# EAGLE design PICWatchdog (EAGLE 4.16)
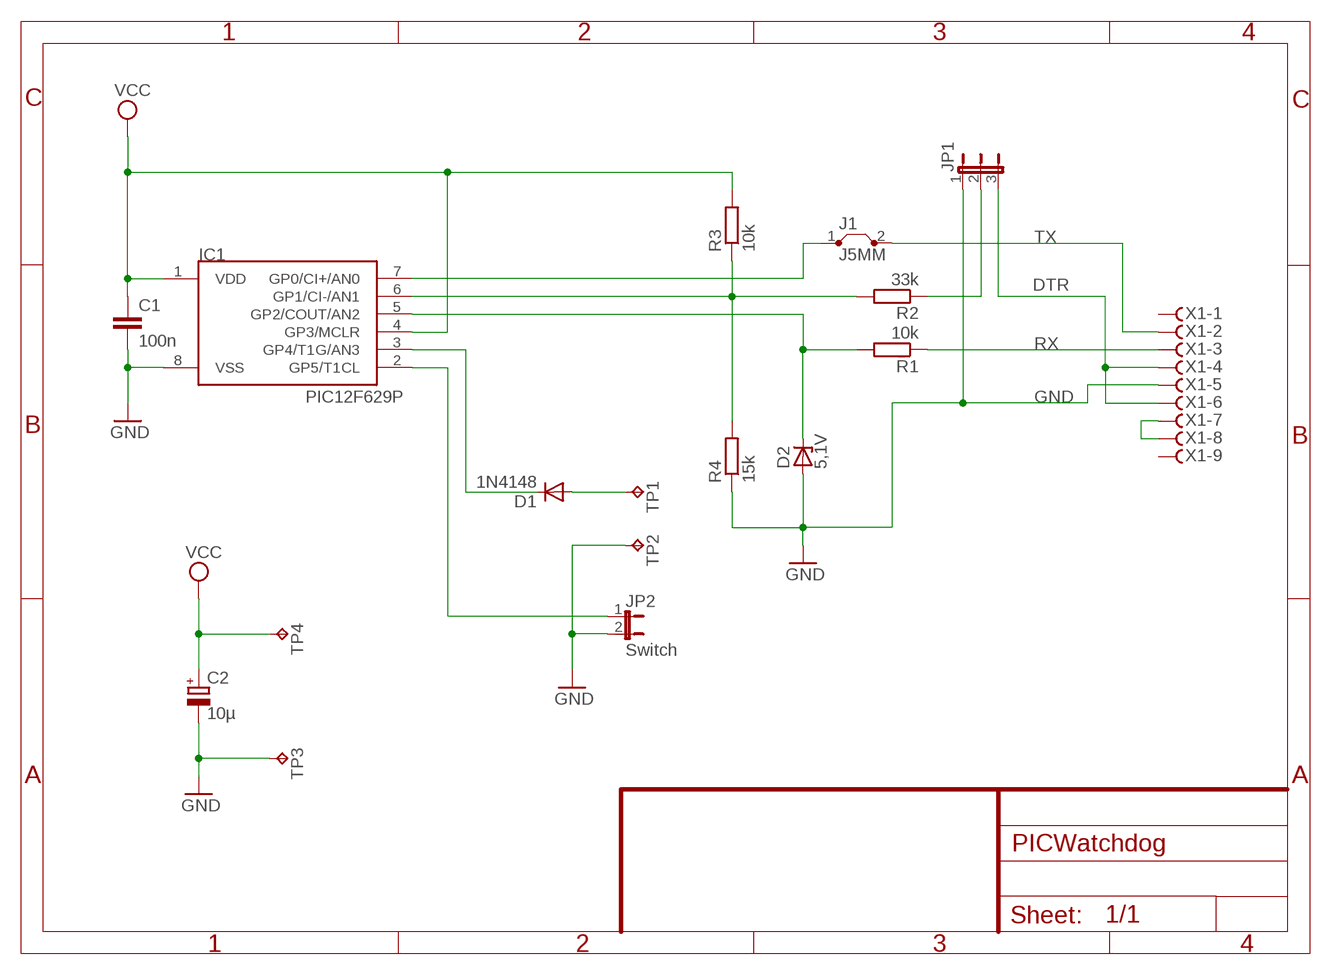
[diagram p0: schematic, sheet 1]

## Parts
C1  100n  C-EU050-030X075  [C050-030X075]
C2  10µ  CPOL-EUE2.5-6  [E2,5-6]
D1  1N4148  [DO35-10]
D2  5,1V  ZENER-DIODEDO34-7  [DO34Z7]
IC1  PIC12F629P  [DIL8]
J1  J5MM  [05]
JP1  JP2E  [JP2]
JP2  Switch  JP1E  [JP1]
R1  10k  R-EU_0207/12  [0207/12]
R2  33k  R-EU_0207/12  [0207/12]
R3  10k  R-EU_0207/12  [0207/12]
R4  15k  R-EU_0207/12  [0207/12]
TP1  TPPAD1-17Y  [P1-17Y]
TP2  TPPAD1-17Y  [P1-17Y]
TP3  TPPAD1-17Y  [P1-17Y]
TP4  TPPAD1-17Y  [P1-17Y]
X1  F09HPS  [F09HP]

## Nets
DTR: JP1.3 X1.4(-4:F) X1.6(-6:F)
GND: C1.2 C2.- D2.A IC1.8(VSS) JP1.1 JP2.2 R4.1 TP2.1(TP) TP3.1(TP) X1.5(-5:F)
N$1: D2.C IC1.5(GP2/COUT/AN2) R1.2
N$2: D1.C IC1.3(GP4/T1G/AN3)
N$3: JP1.2 R2.1
N$4: IC1.6(GP1/CI-/AN1) R2.2 R3.1 R4.2
N$6: X1.7(-7:F) X1.8(-8:F)
N$7: IC1.2(GP5/T1CL) JP2.1
N$8: D1.A TP1.1(TP)
RX: R1.1 X1.3(-3:F)
TX: IC1.7(GP0/CI+/AN0) J1.1 J1.2 X1.2(-2:F)
VCC: C1.1 C2.+ IC1.1(VDD) IC1.4(GP3/MCLR) R3.2 TP4.1(TP)
Unconnected: X1.1(-1:F) X1.9(-9:F) X1.G1(-G:G1) X1.G2(-G:G2)

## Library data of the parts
C1 = rcl:C-EU: CAPACITOR, European symbol
C2 = rcl:CPOL-EU: POLARIZED CAPACITOR, European symbol
D1 = diode:1N4148: DIODE
D2 = diode:ZENER-DIODE: Z-Diode
IC1 = microchip-5:PIC12F6*: uPC nW 1k Program Flash memory 2x Timer Comparator 10b A/D converter/ 4xIN
J1 = jumper:J: Bridge
JP1 = jumper:JP2E: JUMPER
JP2 = jumper:JP1E: JUMPER
R1-R4 = rcl:R-EU_: RESISTOR, European symbol
TP1-TP4 = testpad:TP
X1 = con-subd:F09HPS: SUB-D

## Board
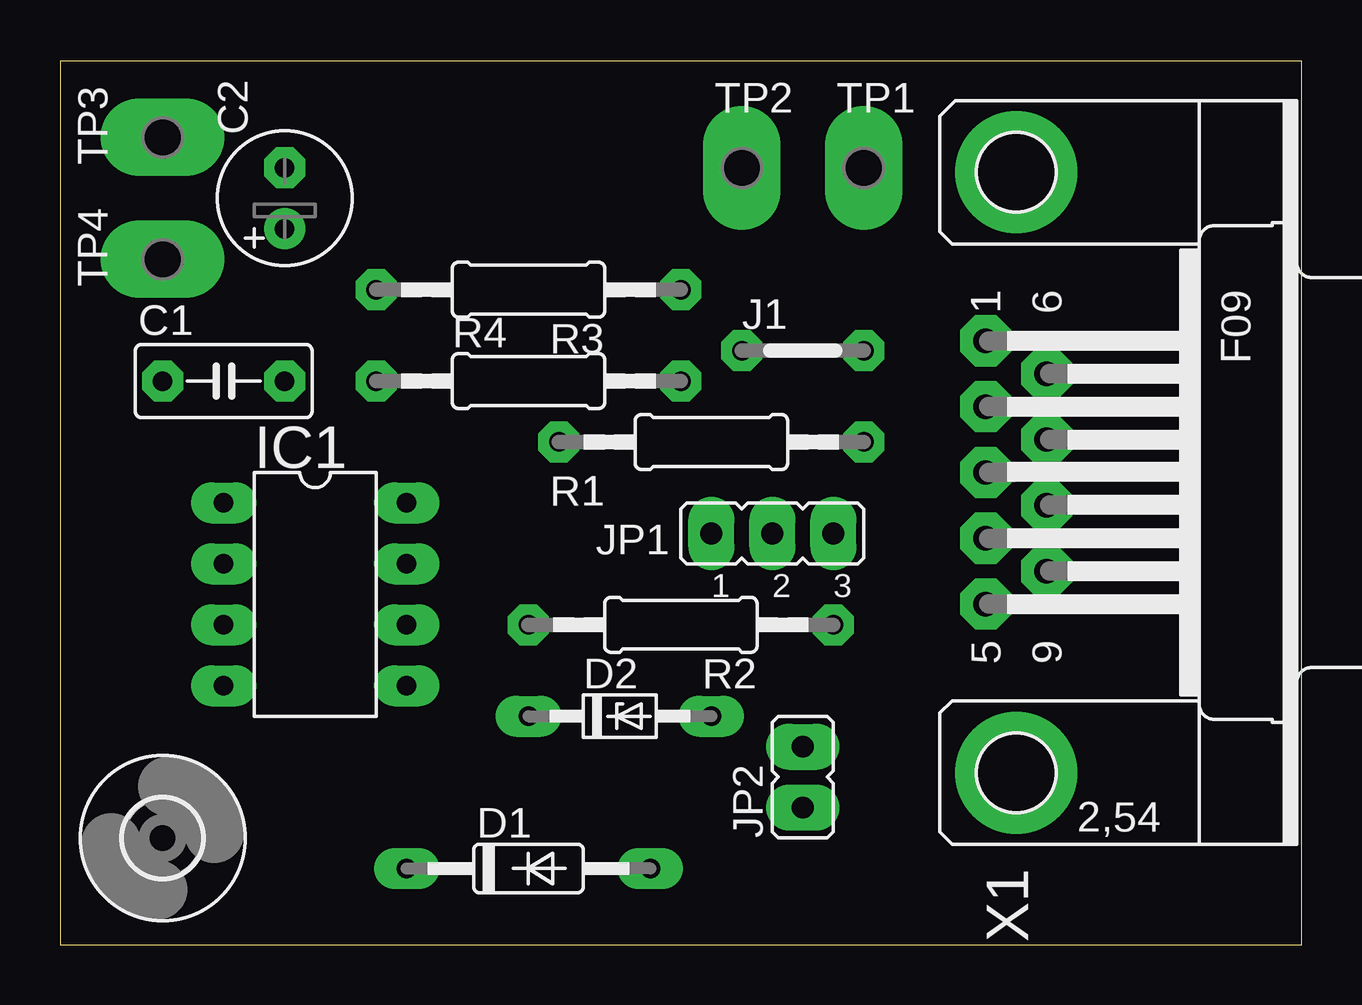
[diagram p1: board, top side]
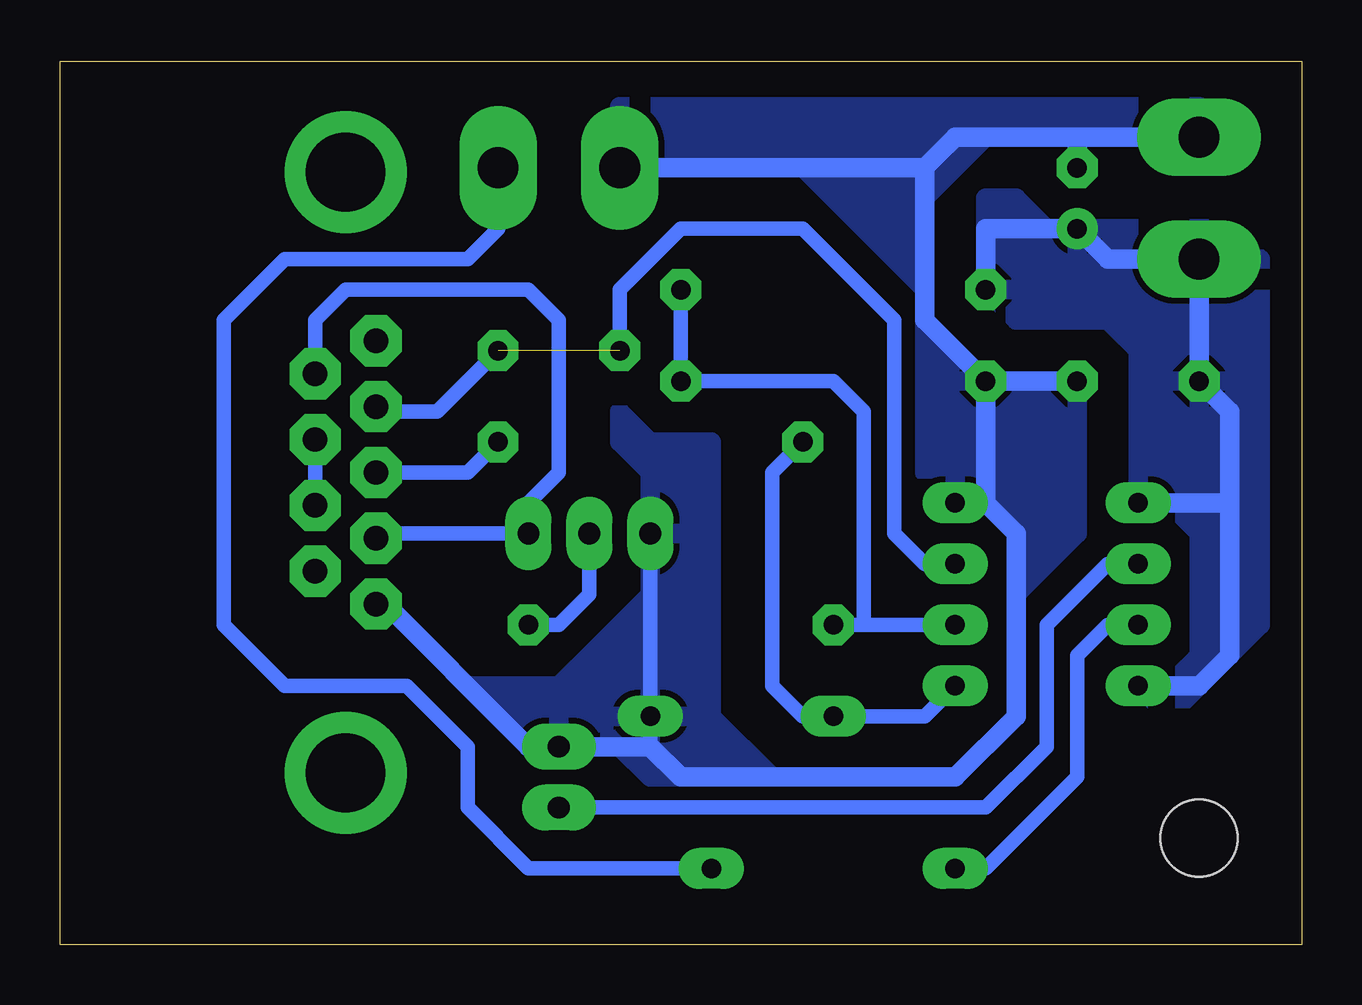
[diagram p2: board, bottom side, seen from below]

Size 51.74 x 36.82 mm. Coordinates in mm from the lower left corner, seen from the top.
Outline: 0,0 51.74,0 51.74,36.82 0,36.82 0,0
Copper layers (1*16): Top 0.035mm / dielectric 1.5mm / Bottom 0.035mm
Design rules "single-layer": minimum track width 12mil, minimum drill 6mil, track to track 8mil, track to pad 8mil, pad to pad 8mil, via to via 8mil, smd to smd 8mil, copper to edge 24mil, drill to drill 8mil, minimum pad ring 16mil, minimum via ring 8mil, stop-mask expansion 4mil, vias tented up to drill 0mil, thermal gap 10mil

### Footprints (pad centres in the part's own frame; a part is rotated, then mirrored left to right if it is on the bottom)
C050-030X075 = drill 0.813 octagon: 1 -2.54,0; 2 2.54,0
E2,5-6 = drill 0.813 pad 1.6 round: + -1.27,0 | drill 0.813 pad 1.6 octagon: - 1.27,0
DO35-10 = drill 0.813 long: A 5.08,0; C -5.08,0
DO34Z7 = drill 0.813 long: A 3.81,0; C -3.81,0
DIL8 = drill 0.813 long: 1 -3.81,-3.81; 2 -1.27,-3.81; 3 1.27,-3.81; 4 3.81,-3.81; 5 3.81,3.81; 6 1.27,3.81; 7 -1.27,3.81; 8 -3.81,3.81
05 = drill 0.813 pad 1.6 octagon: 1 -2.54,0; 2 2.54,0
JP2 = drill 0.914 long: 1 -2.54,0; 2 0,0; 3 2.54,0
JP1 = drill 0.914 long: 1 0,-1.27; 2 0,1.27
0207/12 = drill 0.813 octagon: 1 -6.35,0; 2 6.35,0
P1-17Y = drill 1.702 pad 2.121 long: 1 0,0
3,2 = hole 3.2: 0,0
F09HP = drill 1.016 octagon: 1 -5.486,-1.27; 2 -2.743,-1.27; 3 0,-1.27; 4 2.743,-1.27; 5 5.486,-1.27; 6 -4.115,1.27; 7 -1.372,1.27; 8 1.372,1.27; 9 4.115,1.27 | drill 3.302 pad 5.08 round: G1 -12.522,0; G2 12.522,0

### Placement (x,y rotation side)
C1  6.82,23.49 0 top
C2  9.36,31.11 90 top
D1  19.52,3.17 0 top
D2  23.33,9.52 0 top
IC1  10.63,14.6 270 top
J1  30.95,24.76 0 top
JP1  29.68,17.14 0 top
JP2  30.95,6.98 0 top
R1  27.14,20.95 180 top
R2  25.87,13.33 180 top
R3  19.52,27.3 180 top
R4  19.52,23.49 0 top
TP1  33.49,32.38 0 top
TP2  28.41,32.38 0 top
TP3  4.28,33.65 90 top
TP4  4.28,28.57 90 top
U$1  [3,2]  4.28,4.44 0 top
X1  39.84,19.68 270 top

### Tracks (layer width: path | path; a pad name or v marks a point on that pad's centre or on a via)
DTR
  Bottom 0.61: 38.57,17.14 36.03,17.14 | X1.6 41.11,26.03 39.84,27.3 32.22,27.3 30.95,26.03 30.95,19.68 32.22,18.41 JP1.3 38.57,17.14 | 38.57,17.14 X1.4
GND
  Bottom 0.61: 27.14,8.25 D2.A JP1.1
  Bottom 0.813: 9.36,33.65 TP3.1 | 15.71,32.38 15.71,26.03 R4.1 | 15.71,32.38 14.44,33.65 9.36,33.65 | 9.36,33.65 C2.- | R4.1 C1.2 | 13.17,18.41 R4.1 | 13.17,18.41 IC1.8 | 13.17,18.41 11.9,17.14 11.9,9.52 14.44,6.98 25.87,6.98 27.14,8.25 JP2.2 32.22,8.25 38.57,14.6 X1.5 | 15.71,32.38 TP2.1
  pour Bottom: 9.36,23.49 9.36,17.14 11.9,14.6 11.9,17.14 13.17,18.41 14.44,18.41 15.71,19.68 15.71,26.03 13.17,23.49
  pour Bottom: 4.28,33.65 4.28,34.92 28.41,34.92 28.41,31.11 27.14,32.38 20.79,32.38 15.71,27.3 15.71,31.11 13.17,33.65
  pour Bottom: 22.06,6.98 24.6,9.52 24.6,20.95 27.14,20.95 28.41,22.22 28.41,20.95 27.14,19.68 27.14,14.6 30.95,10.79 34.76,10.79 32.22,8.25 28.41,8.25 27.14,6.98
N$1
  Bottom 0.61: IC1.5 15.71,9.52 D2.C 20.79,9.52 22.06,10.79 22.06,19.68 R1.2
N$2
  Bottom 0.61: IC1.3 8.09,13.33 9.36,12.06 9.36,6.98 13.17,3.17 D1.C
N$3
  Bottom 0.61: JP1.2 29.68,14.6 30.95,13.33 R2.1
N$4
  Bottom 0.61: R3.1 R4.2 19.52,23.49 18.25,22.22 18.25,13.33 | IC1.6 18.25,13.33 | 18.25,13.33 R2.2
N$6
  Bottom 0.61: X1.8 X1.7
N$7
  Bottom 0.61: IC1.2 8.09,15.87 10.63,13.33 10.63,8.25 13.17,5.71 JP2.1
N$8
  Bottom 0.61: D1.A 32.22,3.17 34.76,5.71 34.76,8.25 37.3,10.79 42.38,10.79 44.92,13.33 44.92,26.03 42.38,28.57 34.76,28.57 33.49,29.84 TP1.1
RX
  Bottom 0.61: R1.1 34.76,19.68 X1.3
TX  (1 unrouted)
  Bottom 0.61: IC1.7 15.71,15.87 16.98,17.14 16.98,26.03 20.79,29.84 25.87,29.84 28.41,27.3 J1.1 | J1.2 36.03,22.22 38.57,22.22 X1.2
VCC
  Bottom 0.813: R3.2 13.17,29.84 C2.+ 8.09,28.57 TP4.1 C1.1 3.01,22.22 3.01,18.41 | IC1.4 4.28,10.79 3.01,12.06 3.01,18.41 | 3.01,18.41 IC1.1
  pour Bottom: 1.74,28.57 1.74,13.33 5.55,9.52 6.82,10.79 5.55,10.79 4.28,12.06 4.28,17.14 5.55,18.41 6.82,18.41 6.82,24.76 8.09,26.03 11.9,26.03 13.17,27.3 13.17,31.11 11.9,31.11 10.63,29.84 3.01,29.84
